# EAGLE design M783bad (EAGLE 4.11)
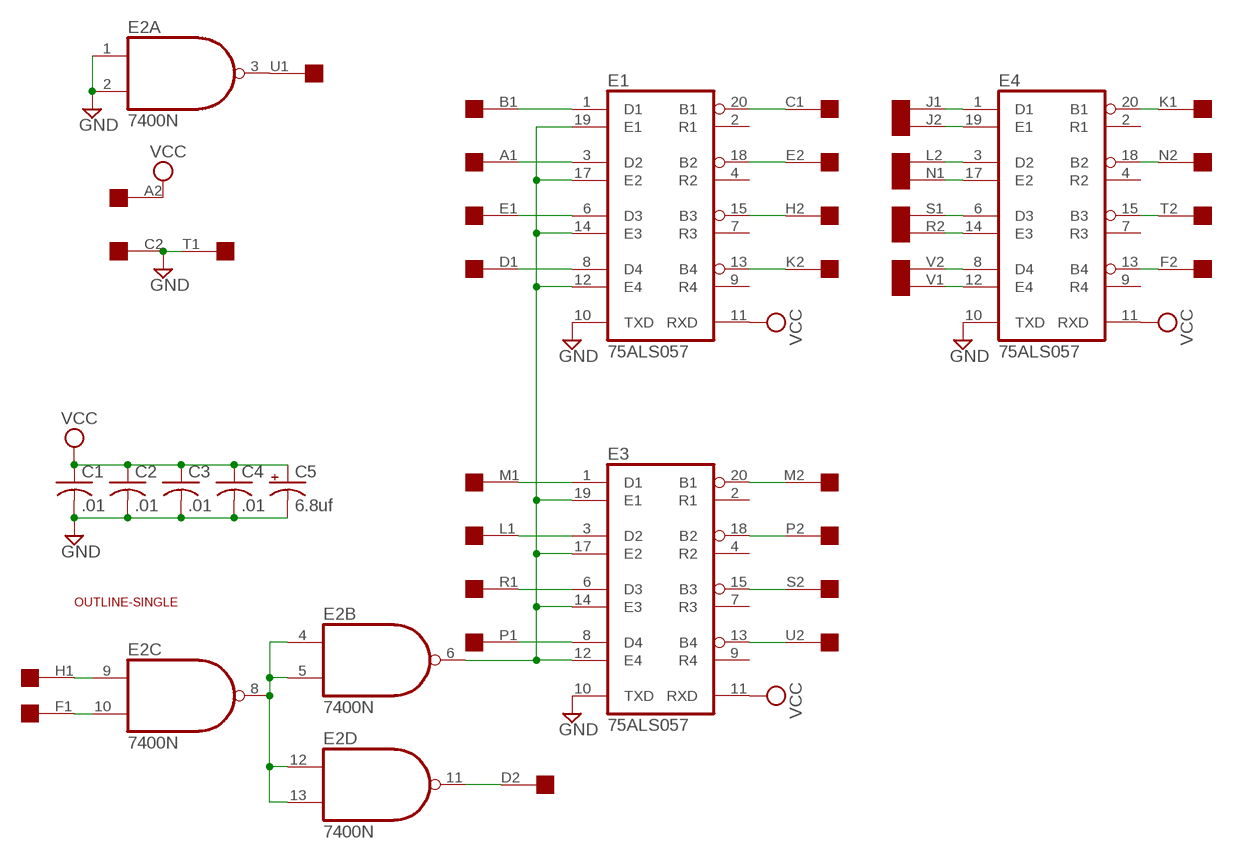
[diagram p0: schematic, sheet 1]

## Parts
C1  .01  C-US050-025X075  [C050-025X075]
C2  .01  C-US050-025X075  [C050-025X075]
C3  .01  C-US050-025X075  [C050-025X075]
C4  .01  C-US050-025X075  [C050-025X075]
C5  6.8uf  CPOL-USE15-5AXIAL  [E15-5]
E1  75ALS057  [DIL20]
E2  7400N  [DIL14]
E3  75ALS057  [DIL20]
E4  75ALS057  [DIL20]
U$1  SINGLE  [EDGE-CON2]
U$2  OUTLINE-SINGLE  [SINGLE]

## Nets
GND: C1.2 C2.2 C3.2 C4.2 C5.- E1.10(TXD) E2.1(A:I0) E2.2(A:I1) E3.10(TXD) E4.10(TXD) U$1.C2 U$1.T1
N$1: E2.3(A:O) U$1.U1
N$2: E1.12(E4) E1.14(E3) E1.17(E2) E1.19(E1) E2.6(B:O) E3.12(E4) E3.14(E3) E3.17(E2) E3.19(E1)
N$3: E3.20(B1) U$1.M2
N$4: E3.18(B2) U$1.P2
N$5: E3.8(D4) U$1.P1
N$6: E3.6(D3) U$1.R1
N$7: E3.15(B3) U$1.S2
N$8: E3.3(D2) U$1.L1
N$9: E3.13(B4) U$1.U2
N$10: E3.1(D1) U$1.M1
N$11: E1.20(B1) U$1.C1
N$12: E1.1(D1) U$1.B1
N$13: E1.18(B2) U$1.E2
N$14: E1.3(D2) U$1.A1
N$15: E1.15(B3) U$1.H2
N$16: E1.6(D3) U$1.E1
N$17: E1.13(B4) U$1.K2
N$18: E1.8(D4) U$1.D1
N$19: E2.11(D:O) U$1.D2
N$20: E4.13(B4) U$1.F2
N$21: E4.15(B3) U$1.T2
N$22: E4.18(B2) U$1.N2
N$23: E4.20(B1) U$1.K1
N$24: E4.1(D1) U$1.J1
N$25: E4.19(E1) U$1.J2
N$26: E4.3(D2) U$1.L2
N$27: E4.17(E2) U$1.N1
N$28: E4.6(D3) U$1.S1
N$29: E4.14(E3) U$1.R2
N$30: E2.4(B:I0) E2.5(B:I1) E2.8(C:O) E2.12(D:I0) E2.13(D:I1)
N$31: E2.9(C:I0) U$1.H1
N$32: E2.10(C:I1) U$1.F1
N$33: E4.8(D4) U$1.V2
N$34: E4.12(E4) U$1.V1
VCC: C1.1 C2.1 C3.1 C4.1 C5.+ E1.11(RXD) E3.11(RXD) E4.11(RXD) U$1.A2
Unconnected: E1.2(R1) E1.4(R2) E1.7(R3) E1.9(R4) E3.2(R1) E3.4(R2) E3.7(R3) E3.9(R4) E4.2(R1) E4.4(R2) E4.7(R3) E4.9(R4) U$1.B2

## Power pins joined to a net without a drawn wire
GND: E1.16(GND) E2.7(P:GND) E3.16(GND) E4.16(GND)
VCC: E1.5(VCC) E2.14(P:VCC) E3.5(VCC) E4.5(VCC)

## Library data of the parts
C1-C4 = rcl:C-US: CAPACITOR, American symbol
C5 = rcl:CPOL-US: POLARIZED CAPACITOR, American symbol
E1 E3 E4 = dec-con:75ALS057: Qbus Compatible Transceiver
E2 = 74xx-jameco:74*00: Quad 2-input NAND gate
U$1 = dec-con:SINGLE: Single-Height DEC board
U$2 = dec-con:OUTLINE-*: Board outlines for DEC boards.

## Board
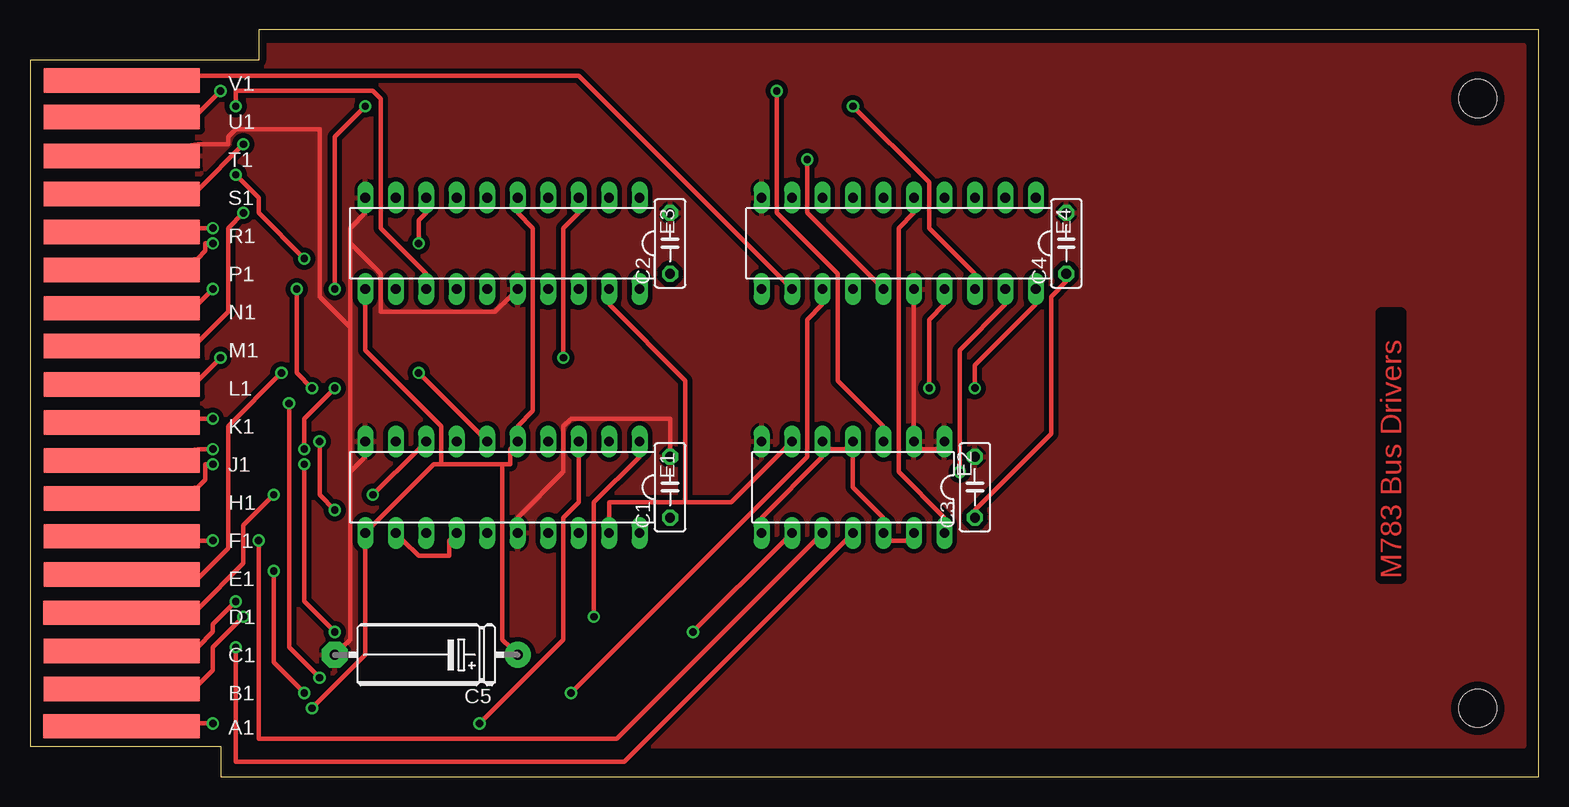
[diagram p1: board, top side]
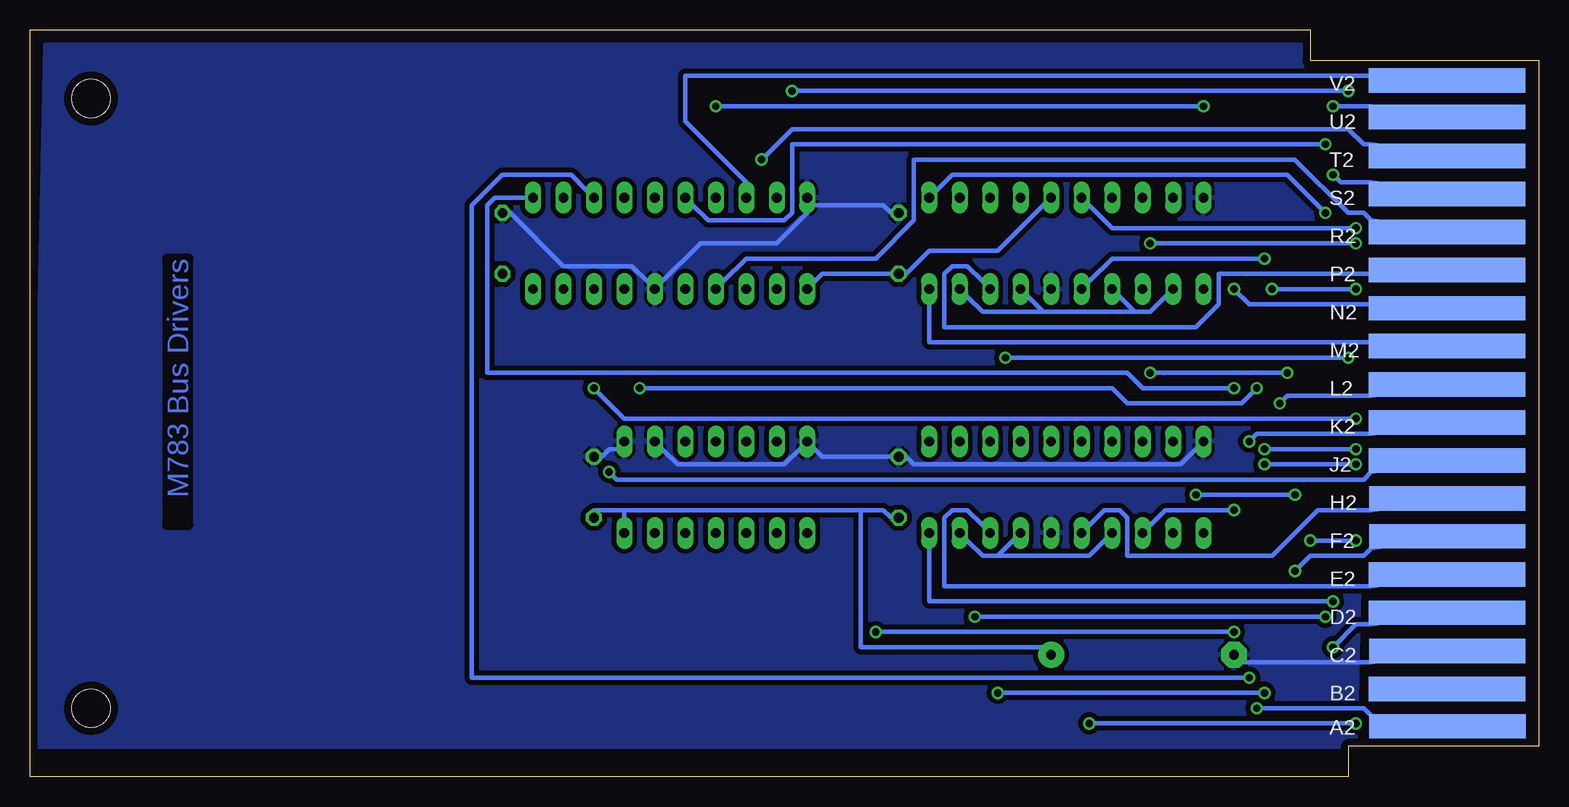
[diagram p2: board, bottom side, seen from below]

Size 125.73 x 62.23 mm. Coordinates in mm from the lower left corner, seen from the top.
Copper layers (1*16): Top 0.035mm / dielectric 1.5mm / Bottom 0.035mm
Design rules "15mils": minimum track width 15mil, minimum drill 24mil, track to track 15mil, track to pad 10mil, pad to pad 10mil, via to via 10mil, smd to smd 10mil, copper to edge 25mil, drill to drill 10mil, minimum pad ring 10mil, minimum via ring 8mil, stop-mask expansion 0mil, vias tented up to drill 0mil, thermal gap 10mil

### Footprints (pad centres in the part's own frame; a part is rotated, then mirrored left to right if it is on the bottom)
C050-025X075 = drill 0.813 octagon: 1 -2.54,0; 2 2.54,0
E15-5 = drill 0.813 pad 2.159 round: + -7.62,0 | drill 0.813 pad 2.159 octagon: - 7.62,0
DIL20 = drill 0.813 long: 1 -8.89,-3.81; 2 -6.35,-3.81; 3 -3.81,-3.81; 4 -1.27,-3.81; 5 1.27,-3.81; 6 3.81,-3.81; 7 6.35,-3.81; 8 8.89,-3.81; 9 11.43,-3.81; 10 13.97,-3.81; 11 13.97,3.81; 12 11.43,3.81; 13 8.89,3.81; 14 6.35,3.81; 15 3.81,3.81; 16 1.27,3.81; 17 -1.27,3.81; 18 -3.81,3.81; 19 -6.35,3.81; 20 -8.89,3.81
DIL14 = drill 0.813 long: 1 -7.62,-3.81; 2 -5.08,-3.81; 3 -2.54,-3.81; 4 0,-3.81; 5 2.54,-3.81; 6 5.08,-3.81; 7 7.62,-3.81; 8 7.62,3.81; 9 5.08,3.81; 10 2.54,3.81; 11 0,3.81; 12 -2.54,3.81; 13 -5.08,3.81; 14 -7.62,3.81
EDGE-CON2 = smd 13.017 x 2.032: A1 7.633,4.207; B1 7.639,7.327; C1 7.636,10.489; D1 7.633,13.665; E1 7.642,16.84; F1 7.642,20.041; H1 7.642,23.19; J1 7.642,26.34; K1 7.642,29.515; L1 7.642,32.69; M1 7.642,35.89; N1 7.642,39.04; P1 7.642,42.24; R1 7.642,45.39; S1 7.642,48.565; T1 7.642,51.74; U1 7.642,54.966; V1 7.642,58.026 | smd 13.017 x 2.032 bottom: A2 7.614,4.207; B2 7.642,7.328; C2 7.617,10.49; D2 7.642,13.665; E2 7.642,16.84; F2 7.617,20.041; H2 7.617,23.19; J2 7.642,26.34; K2 7.642,29.515; L2 7.642,32.69; M2 7.642,35.89; N2 7.642,39.04; P2 7.642,42.24; R2 7.642,45.39; S2 7.642,48.565; T2 7.642,51.74; U2 7.642,54.966; V2 7.642,58.026
SINGLE = hole 3.175: 120.65,56.515; 120.65,5.715

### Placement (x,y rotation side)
C1  53.34,24.13 90 top
C2  53.34,44.45 90 top
C3  78.74,24.13 90 top
C4  86.36,44.45 90 top
C5  33.02,10.16 180 top
E1  41.91,24.13 180 top
E2  68.58,24.13 180 top
E3  41.91,44.45 180 top
E4  74.93,44.45 180 top
U$1  0,0 0 top
U$2  0,0 0 top

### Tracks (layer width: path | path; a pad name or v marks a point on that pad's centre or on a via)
GND
  Top 0.381: E1.16 40.64,21.59 44.45,25.4 44.45,29.21 45.09,29.84 53.34,29.84 53.34,27.3 C1.2 | E2.1 75.57,27.3 74.3,27.3 E2.2 73.66,29.21 73.66,39.37 E4.16 | 26.67,25.4 27.94,26.67 E1.10 | 26.67,25.4 26.67,11.43 26.04,10.79 C5.- | 26.67,25.4 26.67,37.47 | 26.67,37.47 26.67,44.45 | 26.67,44.45 26.67,45.72 27.94,46.99 E3.10 | 26.67,44.45 29.21,41.91 29.21,38.73 38.74,38.73 40.01,40.01 E3.16 | 26.67,37.47 24.13,40.01 24.13,53.98 17.15,53.98 16.51,53.34 16.51,52.7 13.97,52.7 U$1.T1
  Bottom 0.381: C2.2 53.98,46.99 54.61,47.62 60.33,47.62 E4.10 60.96,46.99 63.5,44.45 69.85,44.45 73.03,41.27 E4.16 74.3,41.27 75.57,42.55 81.28,42.55 85.73,46.99 C4.2 | C3.2 78.11,26.67 77.47,27.3 76.84,27.3 E2.1 | E2.2 73.03,27.3 71.76,26.04 62.87,26.04 61.6,27.3 E2.7 60.33,27.3 59.69,26.67 53.98,26.67 C1.2 52.71,26.67 52.07,26.04 29.85,26.04 28.58,27.3 E1.10 | U$1.C2 13.97,9.53 24.77,9.53 C5.-
  pour Bottom (isolate 0.406): 13.97,60.96 124.46,60.96 125.73,2.54 15.24,2.54
  pour Top (isolate 0.406): 13.97,60.96 124.46,60.96 124.46,2.54 13.97,2.54
N$1  (via drill 0.61)
  Top 0.381: v62.23,57.15 62.23,46.99 67.31,41.91 67.31,33.02 71.12,29.21 E2.3 | v15.88,57.15 13.97,55.24 U$1.U1
  Bottom 0.381: v15.88,57.15 v62.23,57.15
N$2
  Top 0.381: E1.12 31.12,19.68 32.39,18.41 34.93,18.41 34.93,19.68 E1.14 | 54.61,22.86 48.26,22.86 48.26,21.59 E1.19 | 54.61,22.86 58.42,22.86 62.87,27.3 E2.6 | 54.61,22.86 54.61,33.02 48.26,39.37 E3.19
  Bottom 0.381: 33.66,38.73 32.39,38.73 31.12,40.01 E3.12 | 33.66,38.73 34.93,40.01 E3.14 | 41.28,38.73 42.55,40.01 E3.17 | 41.28,38.73 33.66,38.73 | 41.28,38.73 46.36,38.73 47.63,40.01 E3.19 | 45.09,18.41 43.82,19.68 E1.17 | 45.09,18.41 46.36,18.41 47.63,19.68 E1.19 | 45.09,18.41 37.47,18.41 36.2,19.68 E1.14
N$3
  Bottom 0.381: E3.20 50.8,39.37 50.8,36.2 13.97,36.2 U$1.M2
N$4
  Bottom 0.381: E3.18 46.36,41.27 47.63,42.55 48.9,42.55 49.53,41.91 49.53,37.47 28.58,37.47 26.67,39.37 26.67,41.91 13.97,41.91 U$1.P2
N$5  (via drill 0.61)
  Top 0.381: v32.39,44.45 32.39,46.35 33.02,46.99 E3.8 | v15.24,44.45 14.61,44.45 14.61,43.81 13.97,43.18 U$1.P1
  Bottom 0.381: v15.24,44.45 v32.39,44.45
N$6  (via drill 0.61)
  Top 0.381: v15.24,45.72 13.97,45.72 U$1.R1
  Bottom 0.381: v15.24,45.72 35.56,45.72 37.47,47.62 E3.6
N$7  (via drill 0.61)
  Top 0.381: v22.86,43.18 19.05,46.99 19.05,48.26 v17.15,50.16
  Bottom 0.381: v22.86,43.18 35.56,43.18 37.47,41.27 E3.15 | v17.15,50.16 16.51,49.53 13.97,49.53 U$1.S2
N$8  (via drill 0.61)
  Top 0.381: v44.45,34.92 44.45,45.72 45.72,46.99 E3.3 | v15.88,34.92 13.97,33.02 U$1.L1
  Bottom 0.381: v15.88,34.92 v44.45,34.92
N$9  (via drill 0.61)
  Top 0.381: v17.15,55.88 17.15,57.15 28.58,57.15 29.21,56.52 29.21,45.72 33.02,41.91 E3.13
  Bottom 0.381: v17.15,55.88 13.97,55.88 U$1.U2
N$10  (via drill 0.61)
  Top 0.381: v17.78,46.99 16.51,45.72 16.51,38.73 13.97,36.2 U$1.M1
  Bottom 0.381: v17.78,46.99 20.96,50.16 48.9,50.16 50.17,48.9 E3.1
N$11  (via drill 0.61)
  Top 0.381: v17.15,14.61 15.24,12.7 15.24,12.06 13.97,10.79 U$1.C1
  Bottom 0.381: v17.15,14.61 50.8,14.61 50.8,19.05 E1.20
N$12  (via drill 0.61)
  Top 0.381: v46.99,13.34 46.99,22.86 50.8,26.67 E1.1 | v17.78,13.34 15.24,10.79 15.24,8.89 13.97,7.62 U$1.B1
  Bottom 0.381: v17.78,13.34 v46.99,13.34
N$13
  Bottom 0.381: E1.18 46.36,20.95 47.63,22.23 48.9,22.23 49.53,21.59 49.53,15.88 13.97,15.88 U$1.E2
N$14  (via drill 0.61)
  Top 0.381: v37.47,4.45 44.45,11.43 44.45,21.59 45.72,22.86 45.72,26.67 E1.3 | v15.24,4.45 13.97,4.45 U$1.A1
  Bottom 0.381: v15.24,4.45 v37.47,4.45
N$15
  Bottom 0.381: E1.15 37.47,20.95 36.2,22.23 34.93,22.23 34.29,21.59 34.29,18.41 22.23,18.41 18.42,22.23 13.97,22.23 U$1.H2
N$16  (via drill 0.61)
  Top 0.381: v32.39,33.66 37.47,28.57 E1.6 | v20.96,33.66 16.51,29.21 16.51,19.05 13.97,16.51 U$1.E1
  Bottom 0.381: v20.96,33.66 v32.39,33.66
N$17  (via drill 0.61)
  Top 0.381: v25.4,22.23 24.13,23.5 v24.13,27.94
  Bottom 0.381: v25.4,22.23 31.12,22.23 32.39,20.95 E1.13 | v24.13,27.94 23.5,28.57 13.97,28.57 U$1.K2
N$18  (via drill 0.61)
  Top 0.381: v28.58,23.5 32.39,27.3 E1.8 | v20.32,23.5 17.78,20.95 17.78,17.78 13.97,13.97 U$1.D1
  Bottom 0.381: v20.32,23.5 v28.58,23.5
N$19  (via drill 0.61)
  Top 0.381: v17.15,10.79 17.15,1.27 49.53,1.27 67.95,19.68 E2.11
  Bottom 0.381: v17.15,10.79 15.24,12.7 13.97,12.7 U$1.D2
N$20  (via drill 0.61)
  Top 0.381: v45.09,6.99 64.77,26.67 64.77,38.1 66.04,39.37 E4.13 | v22.86,6.99 20.32,9.53 v20.32,17.14
  Bottom 0.381: v22.86,6.99 v45.09,6.99 | v20.32,17.14 19.05,18.41 14.61,18.41 13.97,19.05 U$1.F2
N$21  (via drill 0.61)
  Top 0.381: v64.77,51.44 64.77,46.99 70.49,41.27 E4.15
  Bottom 0.381: v64.77,51.44 62.23,53.98 15.88,53.98 14.61,52.7 13.97,52.7 U$1.T2
N$22  (via drill 0.61)
  Top 0.381: v68.58,55.88 74.93,49.53 74.93,45.72 78.74,41.91 E4.18 | v27.94,55.88 25.4,53.34 v25.4,40.64
  Bottom 0.381: v27.94,55.88 v68.58,55.88 | v25.4,40.64 24.13,39.37 13.97,39.37 U$1.N2
N$23  (via drill 0.61)
  Top 0.381: v78.74,32.38 78.74,34.29 83.82,39.37 E4.20 | v15.24,29.84 13.97,29.84 U$1.K1
  Bottom 0.381: v78.74,32.38 76.2,29.84 v15.24,29.84
N$24  (via drill 0.61)
  Top 0.381: v25.4,32.38 22.86,29.84 v22.86,27.3 | v15.24,27.3 13.97,27.3 U$1.J1
  Bottom 0.381: v25.4,32.38 33.02,32.38 34.29,33.66 87.63,33.66 87.63,47.62 87,48.26 84.46,48.26 E4.1 | v15.24,27.3 v22.86,27.3
N$25  (via drill 0.61)
  Top 0.381: v77.47,25.4 77.47,35.56 81.28,39.37 E4.19
  Bottom 0.381: v77.47,25.4 76.84,24.77 14.61,24.77 13.97,25.4 U$1.J2
N$26  (via drill 0.61)
  Top 0.381: v24.13,8.26 21.59,10.79 v21.59,31.11
  Bottom 0.381: v24.13,8.26 88.9,8.26 88.9,47.62 86.36,50.16 80.65,50.16 79.38,48.9 E4.3 | v21.59,31.11 20.96,31.75 13.97,31.75 U$1.L2
N$27  (via drill 0.61)
  Top 0.381: v74.93,32.38 74.93,38.1 76.2,39.37 E4.17 | v23.5,32.38 22.23,33.66 v22.23,40.64 | v15.24,40.64 13.97,39.37 U$1.N1
  Bottom 0.381: v74.93,32.38 35.56,32.38 34.29,31.11 24.77,31.11 v23.5,32.38 | v15.24,40.64 v22.23,40.64
N$28  (via drill 0.61)
  Top 0.381: v17.78,52.7 13.97,48.9 U$1.S1
  Bottom 0.381: v17.78,52.7 62.23,52.7 62.23,46.99 62.87,46.35 69.22,46.35 70.49,47.62 E4.6
N$29
  Bottom 0.381: E4.14 67.95,41.27 66.04,43.18 55.25,43.18 52.07,46.35 52.07,51.44 20.32,51.44 15.88,46.99 14.61,46.99 13.97,46.35 U$1.R2
N$30
  Top 0.381: E2.13 73.03,19.68 71.76,19.68 E2.12 71.12,21.59 68.58,24.13 68.58,26.67 E2.4 67.95,27.3 66.68,27.3 E2.5 66.04,26.67 60.96,21.59 E2.8
N$31  (via drill 0.61)
  Top 0.381: v55.25,12.06 62.87,19.68 E2.9 | v25.4,12.06 22.86,14.61 v22.86,26.04 | v15.24,26.04 14.61,26.04 14.61,24.77 13.97,24.13 U$1.H1
  Bottom 0.381: v25.4,12.06 v55.25,12.06 | v15.24,26.04 v22.86,26.04
N$32  (via drill 0.61)
  Top 0.381: v19.05,19.68 19.05,3.17 48.9,3.17 65.41,19.68 E2.10 | v15.24,19.68 13.97,19.68 U$1.F1
  Bottom 0.381: v19.05,19.68 v15.24,19.68
N$33
  Bottom 0.381: E4.8 66.04,49.53 71.12,54.61 71.12,58.42 13.97,58.42 U$1.V2
N$34
  Top 0.381: E4.12 62.87,41.27 45.72,58.42 13.97,58.42 U$1.V1
VCC  (via drill 0.61)
  Top 0.381: E4.5 73.66,46.99 72.39,45.72 72.39,25.4 76.2,21.59 E2.14 | C4.1 86.36,41.27 85.09,40.01 85.09,28.57 78.74,22.23 C3.1 | 39.37,26.04 40.01,26.04 40.01,27.3 E1.5 40.64,29.21 41.91,30.48 41.91,45.72 40.64,46.99 E3.5 | 34.29,26.04 39.37,26.04 | 34.29,26.04 33.66,26.04 28.58,20.95 E1.11 27.94,19.05 27.94,10.16 v23.5,5.71 | 34.29,26.04 34.29,29.21 27.94,35.56 27.94,39.37 E3.11 | 39.37,26.04 39.37,11.43 40.01,10.79 C5.+
  Bottom 0.381: 76.2,22.23 78.74,22.23 C3.1 | 56.52,22.23 76.2,22.23 | 56.52,22.23 54.61,22.23 53.98,21.59 C1.1 | 76.2,22.23 76.2,21.59 E2.14 | E4.11 60.33,41.27 59.69,41.91 53.98,41.91 C2.1 52.71,41.91 50.8,43.81 45.09,43.81 41.28,47.62 E3.5 | v23.5,5.71 14.61,5.71 13.97,5.08 U$1.A2 | 56.52,22.23 56.52,10.79 41.28,10.79 C5.+

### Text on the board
Top: M783 Bus Drivers
Bottom: M783 Bus Drivers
